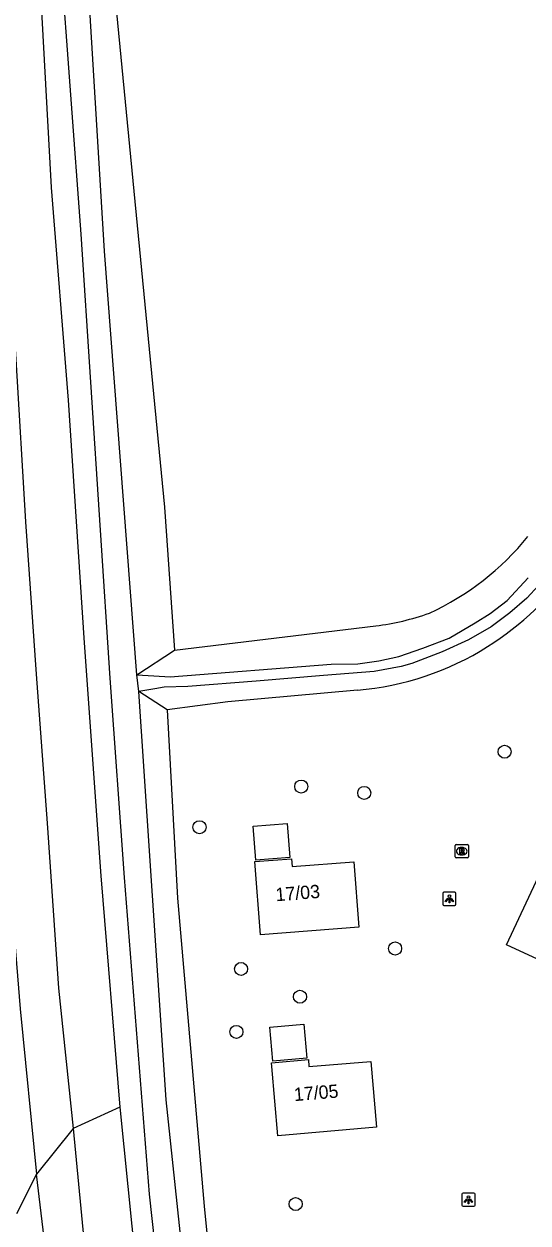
# Model space of a CAD drawing. Extents: x 157793 to 159380, y 380882 to 382313.
# Drawn here: x 157943.1 to 157981, y 381170.1 to 381260.1 of the extents above; entities that cross this region are included whole.
import ezdxf

# ---------------------------------------------------------------- set-up
doc = ezdxf.new("R2010")
doc.units = 0
for name, color, linetype in [('IMGEO_Berm_groen', 7, 'Continuous'), ('IMGEO_Boom', 7, 'Continuous'), ('IMGEO_Grasland_overig', 7, 'Continuous'), ('IMGEO_Groenvoorziening', 7, 'Continuous'), ('IMGEO_Lichtpunt', 7, 'Continuous'), ('IMGEO_Oever', 7, 'Continuous'), ('IMGEO_Pand', 7, 'Continuous'), ('IMGEO_Pand_nummerreeks', 7, 'Continuous'), ('IMGEO_Rioolput', 7, 'Continuous'), ('IMGEO_Waterloop', 7, 'Continuous')]:
    doc.layers.add(name, color=color, linetype=linetype)

msp = doc.modelspace()

# ---------------------------------------------------------------- linework, layer by layer
at = {"layer": 'IMGEO_Berm_groen'}
for points in [[(157917.619, 381403.513), (157918.335, 381397.829), (157920.126, 381384.266), (157922.819, 381367.812), (157924.53, 381352.726), (157925.989, 381339.921), (157927.437, 381326.682), (157929.374, 381311.81), (157931.267, 381297.601), (157932.466, 381287.628), (157933.789, 381277.041), (157934.937, 381266.577), (157936.076, 381255.154), (157937.25, 381243.771), (157938.506, 381233.406), (157939.65, 381222.622), (157940.635, 381210.873), (157941.822, 381198.851), (157942.853, 381186.146), (157944.078, 381173.732)], [(157944.078, 381173.732), (157942.585, 381170.761)]]:
    msp.add_lwpolyline(points, dxfattribs=at)
at = {"layer": 'IMGEO_Boom'}
for centre in [(157979.22, 381205.467), (157963.954, 381202.851), (157968.685, 381202.373), (157956.319, 381199.796), (157970.997, 381190.683), (157959.435, 381189.145), (157963.862, 381187.061), (157959.085, 381184.422), (157963.537, 381171.489)]:
    msp.add_circle(centre, 0.489, dxfattribs=at)
at = {"layer": 'IMGEO_Grasland_overig'}
for points in [[(157939.103, 381294.6), (157939.335, 381287.774), (157939.854, 381277.11), (157940.456, 381266.282), (157941.177, 381255.327), (157941.853, 381245.291), (157942.525, 381234.954), (157943.252, 381222.722), (157944.072, 381211.284), (157944.899, 381200.091), (157945.745, 381187.714), (157946.841, 381177.173)], [(157943.332, 381280.059), (157944.138, 381267.064), (157945.186, 381247.841), (157946.471, 381231.86), (157947.658, 381213.64), (157948.904, 381196.154), (157950.352, 381178.754)], [(157950.352, 381178.754), (157946.841, 381177.173)], [(157950.352, 381178.754), (157951.847, 381163.855), (157954.104, 381147.602), (157956.422, 381130.075), (157957.719, 381121.572), (157958.644, 381117.616), (157961.22, 381107.916), (157963.769, 381099.155), (157967.983, 381088.156), (157968.522, 381086.749), (157971.914, 381078.749), (157974.558, 381073.096), (157977.322, 381067.984), (157980.977, 381061.407), (157984.259, 381055.782), (157989.472, 381047.992), (157991.634, 381044.218), (157992.625, 381042.334), (157993.206, 381041.178), (157993.84, 381040.215), (157995.154, 381038.848), (157995.969, 381038.005)], [(157946.841, 381177.173), (157944.078, 381173.732)], [(157946.841, 381177.173), (157948.034, 381164.626), (157949.339, 381151.708), (157950.768, 381140.863), (157952.404, 381130.028), (157954.301, 381119.995), (157956.453, 381110.519), (157958.92, 381100.739), (157960.612, 381095.909), (157963.87, 381086.675), (157966.563, 381080.385), (157969.664, 381073.742), (157973.677, 381066.047)], [(157967.318, 381071.349), (157964.872, 381076.248), (157962.772, 381080.813), (157960.655, 381085.727), (157959.04, 381090.499), (157957.871, 381094.508), (157955.317, 381102.987), (157953.331, 381110.198), (157951.232, 381118.587), (157950.064, 381125.988), (157948.596, 381134.164), (157947.349, 381143.571), (157946.215, 381152.965), (157945.298, 381163.703), (157944.078, 381173.732)]]:
    msp.add_lwpolyline(points, dxfattribs=at)
at = {"layer": 'IMGEO_Groenvoorziening'}
for points in [[(157948.933, 381280.373), (157949.593, 381266.166), (157953.69, 381223.825), (157954.432, 381213.092)], [(157954.432, 381213.092), (157969.542, 381214.914)], [(157968.184, 381210.096), (157958.438, 381209.209), (157953.904, 381208.601)], [(157953.904, 381208.601), (157954.667, 381194.473), (157956.666, 381171.336), (157958.091, 381157.039), (157961.056, 381135.277), (157963.956, 381120.521), (157969.049, 381101.066), (157973.397, 381089.261), (157976.609, 381081.434)]]:
    msp.add_lwpolyline(points, dxfattribs=at)
for centre, radius, start, end in [((157964.943, 381234.618), 20.634, 294.74415, 320.97792), ((157966.134, 381232.251), 22.273, 302.02606, 325.21312), ((157967.302, 381233.234), 18.457, 276.96953, 289.88451), ((157966.42, 381231.563), 21.539, 274.69766, 302.35174)]:
    msp.add_arc(centre, radius, start, end, dxfattribs=at)
at = {"layer": 'IMGEO_Lichtpunt'}
for p, q in [((157974.573, 381194.812), (157974.573, 381194.005)), ((157974.573, 381194.812), (157974.573, 381194.005)), ((157975.475, 381194.907), (157974.667, 381194.907)), ((157975.475, 381194.907), (157974.667, 381194.907)), ((157975.569, 381194.005), (157975.569, 381194.812)), ((157975.569, 381194.005), (157975.569, 381194.812)), ((157974.667, 381193.911), (157975.475, 381193.911)), ((157974.667, 381193.911), (157975.475, 381193.911)), ((157976.003, 381172.219), (157976.003, 381171.412)), ((157976.003, 381172.219), (157976.003, 381171.412)), ((157976.905, 381172.314), (157976.097, 381172.314)), ((157976.905, 381172.314), (157976.097, 381172.314)), ((157976.999, 381171.412), (157976.999, 381172.219)), ((157976.999, 381171.412), (157976.999, 381172.219)), ((157976.097, 381171.318), (157976.905, 381171.318)), ((157976.097, 381171.318), (157976.905, 381171.318))]:
    msp.add_line(p, q, dxfattribs=at)
for points in [[(157974.947, 381194.476), (157974.986, 381194.448), (157974.798, 381194.186), (157974.76, 381194.213), (157974.947, 381194.476)], [(157975.049, 381194.428), (157975.096, 381194.428), (157975.096, 381194.106), (157975.049, 381194.106), (157975.049, 381194.428)], [(157975.159, 381194.448), (157975.197, 381194.475), (157975.384, 381194.213), (157975.345, 381194.185), (157975.159, 381194.448)], [(157976.377, 381171.883), (157976.416, 381171.855), (157976.228, 381171.593), (157976.19, 381171.62), (157976.377, 381171.883)], [(157976.479, 381171.835), (157976.526, 381171.835), (157976.526, 381171.513), (157976.479, 381171.513), (157976.479, 381171.835)], [(157976.589, 381171.855), (157976.627, 381171.882), (157976.814, 381171.62), (157976.775, 381171.592), (157976.589, 381171.855)]]:
    msp.add_lwpolyline(points, dxfattribs=at)
for centre in [(157975.072, 381194.61), (157976.502, 381172.017)]:
    msp.add_circle(centre, 0.0994, dxfattribs=at)
for centre, start, end in [((157974.667, 381194.812), 90, 180), ((157974.667, 381194.812), 90, 180), ((157975.475, 381194.812), 0, 90), ((157975.475, 381194.812), 0, 90), ((157974.667, 381194.005), 180, 270), ((157974.667, 381194.005), 180, 270), ((157975.475, 381194.005), 270, 0), ((157975.475, 381194.005), 270, 360), ((157976.097, 381172.219), 90, 180), ((157976.097, 381172.219), 90, 180), ((157976.905, 381172.219), 0, 90), ((157976.905, 381172.219), 0, 90), ((157976.097, 381171.412), 180, 270), ((157976.097, 381171.412), 180, 270), ((157976.905, 381171.412), 270, 0), ((157976.905, 381171.412), 270, 360)]:
    msp.add_arc(centre, 0.0946, start, end, dxfattribs=at)
at = {"layer": 'IMGEO_Oever'}
for points in [[(157951.626, 381211.249), (157954.432, 381213.092)], [(157953.904, 381208.601), (157951.776, 381209.989)]]:
    msp.add_lwpolyline(points, dxfattribs=at)
at = {"layer": 'IMGEO_Pand'}
for points in [[(157960.559, 381197.327), (157960.359, 381199.88), (157962.911, 381200.084), (157963.111, 381197.527), (157960.559, 381197.327)], [(157968.277, 381192.285), (157960.899, 381191.707), (157960.468, 381197.21), (157963.229, 381197.426), (157963.276, 381196.831), (157967.892, 381197.193), (157968.277, 381192.285)], [(157985.099, 381191.358), (157985.576, 381191.133), (157984.327, 381188.644), (157979.362, 381190.966), (157982.51, 381197.696), (157987.066, 381195.565), (157985.099, 381191.358)], [(157964.373, 381182.445), (157961.818, 381182.219), (157961.592, 381184.774), (157964.154, 381185.001), (157964.373, 381182.445)], [(157969.597, 381177.26), (157962.208, 381176.604), (157961.745, 381181.831), (157961.721, 381182.103), (157964.489, 381182.348), (157964.522, 381181.812), (157969.19, 381182.198), (157969.597, 381177.26)]]:
    msp.add_lwpolyline(points, dxfattribs=at)
at = {"layer": 'IMGEO_Rioolput'}
for p, q in [((157975.5, 381197.564), (157975.5, 381198.416)), ((157975.575, 381198.49), (157976.427, 381198.49)), ((157975.988, 381198.27), (157976.013, 381198.27)), ((157976.501, 381198.416), (157976.501, 381197.564)), ((157976.427, 381197.49), (157975.575, 381197.49)), ((157976.011, 381197.71), (157975.986, 381197.71))]:
    msp.add_line(p, q, dxfattribs=at)
for points in [[(157975.5, 381197.564), (157975.5, 381198.416)], [(157975.575, 381198.49), (157976.427, 381198.49)], [(157976.089, 381198.188), (157975.837, 381198.19), (157975.837, 381197.79)], [(157975.837, 381197.79), (157975.961, 381197.79), (157975.961, 381197.952), (157975.972, 381197.952)], [(157976.015, 381198.109), (157975.961, 381198.109), (157975.961, 381198.028)], [(157975.961, 381198.028), (157976.013, 381198.028)], [(157976.019, 381197.923), (157976.09, 381197.79), (157976.23, 381197.79), (157976.165, 381197.916)], [(157976.501, 381198.416), (157976.501, 381197.564)], [(157976.427, 381197.49), (157975.575, 381197.49)]]:
    msp.add_lwpolyline(points, dxfattribs=at)
for centre, radius, start, end in [((157975.577, 381198.414), 0.0765, 91.55205, 178.44795), ((157975.577, 381198.414), 0.0765, 91.55205, 178.44795), ((157975.971, 381197.899), 0.0533, 26.02933, 88.69889), ((157975.997, 381198.217), 0.19, 274.7715, 282.96867), ((157976.021, 381198.013), 0.0964, 77.00612, 93.18647), ((157976.035, 381198.07), 0.0378, 276.66336, 79.67722), ((157976.088, 381198.078), 0.109, 350.36119, 89.41601), ((157976.086, 381198.078), 0.112, 277.58423, 350.98172), ((157976.07, 381197.863), 0.108, 29.51342, 73.79051), ((157976.425, 381198.414), 0.0765, 1.55205, 88.44795), ((157976.425, 381198.414), 0.0765, 1.55205, 88.44795), ((157975.577, 381197.566), 0.0765, 181.55205, 268.44795), ((157975.577, 381197.566), 0.0765, 181.55205, 268.44795), ((157976.425, 381197.566), 0.0765, 271.55205, 358.44795), ((157976.425, 381197.566), 0.0765, 271.55205, 358.44795)]:
    msp.add_arc(centre, radius, start, end, dxfattribs=at)
for centre, major_axis, ratio, start_param, end_param in [((157975.987, 381197.99), (-0.387, 0.002), 0.722429, 4.712389, 7.853982), ((157976.012, 381197.99), (-0.39, 0.002), 0.717154, 1.570796, 4.712389)]:
    msp.add_ellipse(centre, major_axis=major_axis, ratio=ratio, start_param=start_param, end_param=end_param, dxfattribs=at)
at = {"layer": 'IMGEO_Waterloop'}
for points in [[(157994.736, 381043.033), (157990.832, 381048.744), (157980.887, 381064.91), (157973.374, 381079.353), (157965.169, 381100.228), (157959.887, 381118.158), (157958.251, 381127.609), (157955.004, 381150.088), (157952.562, 381172.238), (157950.691, 381196.021), (157949.616, 381210.978), (157947.442, 381244.345), (157945.886, 381265.31), (157944.557, 381281.595)], [(157951.626, 381211.249), (157949.199, 381243.067), (157947.267, 381274.815), (157946.766, 381282.419)], [(157951.626, 381211.249), (157952.892, 381211.175), (157954.124, 381211.102), (157966.192, 381212.034), (157968.197, 381212.07), (157969.772, 381212.301), (157971.282, 381212.613), (157973.069, 381213.233), (157975.055, 381213.991), (157977.016, 381215.136), (157978.146, 381215.856), (157979.411, 381216.821), (157980.979, 381218.521)], [(157981.769, 381217.947), (157980.898, 381216.997), (157979.623, 381215.908), (157978.21, 381214.858), (157976.498, 381213.858), (157974.533, 381212.962), (157972.257, 381212.1), (157971.457, 381211.866), (157969.419, 381211.486), (157965.618, 381211.195), (157960.579, 381210.762), (157955.442, 381210.375), (157953.661, 381210.316), (157952.96, 381210.194), (157951.776, 381209.989)], [(157951.776, 381209.989), (157951.626, 381211.249)], [(157975.148, 381079.541), (157969.49, 381093.331), (157965.564, 381104.907), (157962.076, 381118.203), (157959.332, 381132.084), (157956.217, 381156.646), (157953.818, 381179.321), (157951.776, 381209.989)]]:
    msp.add_lwpolyline(points, dxfattribs=at)

# ---------------------------------------------------------------- texts
at = {"layer": 'IMGEO_Pand_nummerreeks'}
for s, rotation, p in [('17/03', 4.48626, (157962.062, 381194.228)), ('17/05', 4.7269, (157963.447, 381179.214))]:
    msp.add_text(s, height=1, rotation=rotation, dxfattribs=at).set_placement(p)

doc.saveas('drawing.dxf')
